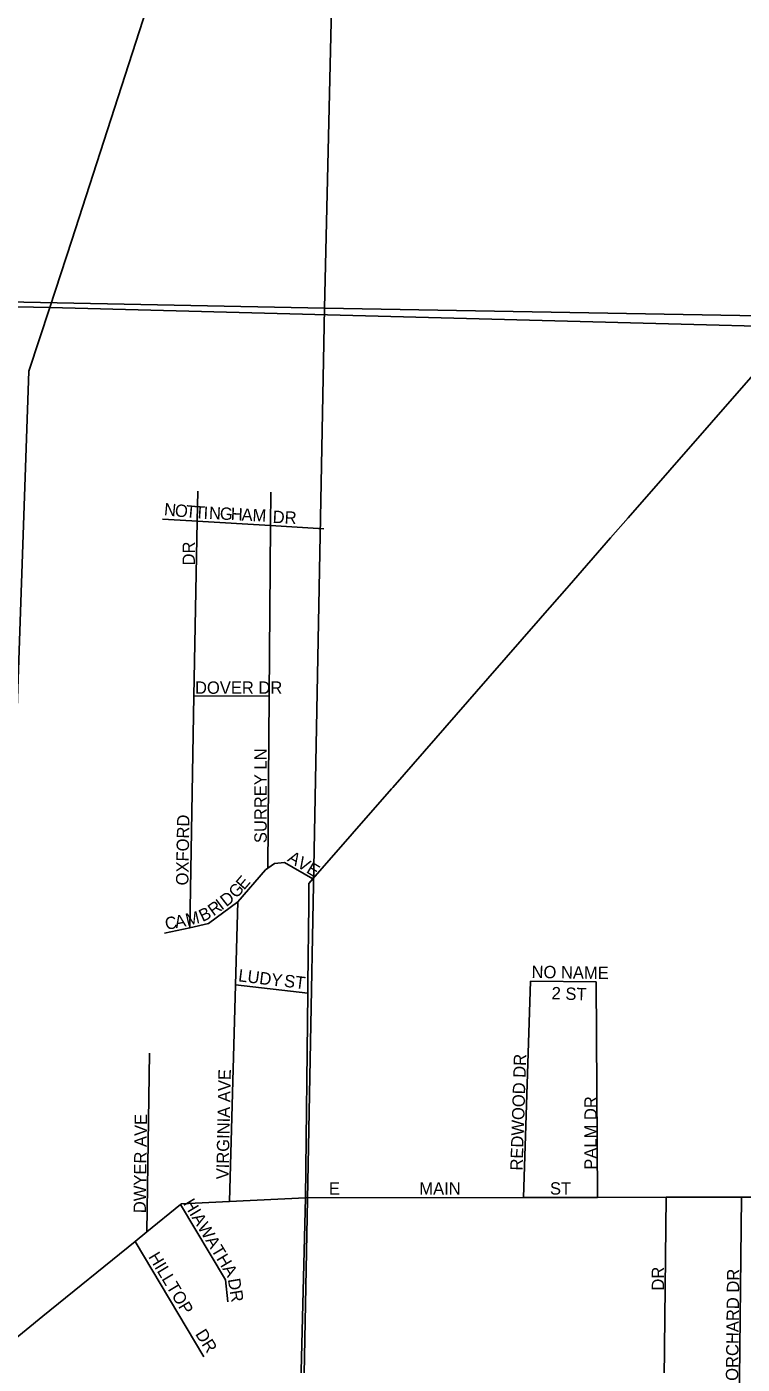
# Model space of a CAD drawing. Extents: x -784 to 1375, y -225 to 440.
# Drawn here: x 310.15 to 321.44, y 368.36 to 389.47 of the extents above; entities that cross this region are included whole.
import ezdxf

# ---------------------------------------------------------------- set-up
doc = ezdxf.new("R2010")
doc.units = 0
for name, color, linetype in [('GM_X_City_Street', 7, 'Continuous'), ('GM_X_City_Street_Text', 7, 'Continuous'), ('GM_X_Section', 7, 'Continuous'), ('GM_X_State_Route', 7, 'Continuous'), ('GM_X_Township_Road', 7, 'Continuous')]:
    doc.layers.add(name, color=color, linetype=linetype)

msp = doc.modelspace()

# ---------------------------------------------------------------- linework, layer by layer
at = {"layer": 'GM_X_City_Street'}
for points in [[(310.857, 386.101), (312.207, 390.273)], [(309.607, 368.471), (309.66, 369.552), (309.713, 371.243), (309.818, 374.657), (309.997, 378.712), (310.179, 384.035), (310.514, 385.041), (310.857, 386.101)], [(309.482, 385.059), (309.482, 385.059), (310.514, 385.041)], [(310.514, 385.041), (320.278, 384.782)], [(312.724, 375.249), (312.788, 378.906), (312.837, 381.666), (312.846, 382.141)], [(313.956, 376.19), (313.976, 378.911), (313.997, 381.597), (314.001, 382.122)], [(312.293, 381.699), (312.756, 381.671)], [(312.756, 381.671), (312.756, 381.671), (312.837, 381.666), (313.997, 381.597), (314.836, 381.547)], [(312.788, 378.906), (313.976, 378.911)], [(312.321, 375.164), (312.724, 375.249), (313.016, 375.313), (313.48, 375.655), (313.916, 376.162), (313.956, 376.19), (314.06, 376.261), (314.217, 376.28), (314.666, 376.021)], [(313.347, 370.925), (313.443, 374.347), (313.48, 375.655)], [(317.989, 370.99), (318.101, 374.403)], [(318.101, 374.403), (319.138, 374.393)], [(319.158, 370.992), (319.138, 374.393)], [(313.443, 374.347), (314.584, 374.213)], [(312.045, 370.446), (312.088, 373.266)], [(314.181, 355.025), (314.287, 359.97), (314.314, 361.184), (314.34, 362.327), (314.37, 363.611), (314.482, 368.251), (314.548, 370.985)], [(314.37, 363.611), (316.423, 363.56), (319.28, 363.488), (319.398, 363.485), (319.707, 363.569), (319.94, 363.718), (320.059, 363.98), (320.099, 364.162), (320.152, 364.4), (320.207, 367.666), (320.241, 370.994)], [(314.548, 370.985), (317.989, 370.99), (319.158, 370.992), (320.241, 370.994), (320.337, 370.994), (320.337, 370.994)], [(320.337, 370.994), (321.428, 370.996), (322.198, 370.997)], [(321.394, 367.658), (321.428, 370.996)], [(313.324, 369.344), (313.285, 369.689), (312.577, 370.877)], [(312.942, 368.475), (311.86, 370.297)]]:
    msp.add_lwpolyline(points, dxfattribs=at)
at = {"layer": 'GM_X_Section'}
msp.add_lwpolyline([(311.752, 405.896), (315.331, 405.821), (314.846, 385.028), (293.747, 385.447), (294.035, 399.712)], dxfattribs=at)
for points in [[(315.331, 405.821), (335.943, 405.436), (335.412, 384.667), (314.846, 385.028)], [(293.747, 385.447), (314.846, 385.028), (314.451, 364.338), (293.485, 364.699)], [(314.846, 385.028), (335.412, 384.667), (334.976, 363.947), (314.451, 364.338)]]:
    msp.add_lwpolyline(points, close=True, dxfattribs=at)
at = {"layer": 'GM_X_State_Route'}
for points in [[(319.641, 381.718), (322.271, 384.729), (322.411, 384.889)], [(319.364, 381.401), (319.641, 381.718)], [(318.672, 380.609), (318.709, 380.65), (319.364, 381.401)], [(318.257, 380.133), (318.291, 380.172), (318.672, 380.609)], [(317.427, 379.182), (318.257, 380.133)], [(315.904, 377.439), (315.925, 377.463), (317.427, 379.182)], [(314.599, 375.613), (314.6, 375.632), (314.603, 375.949), (314.666, 376.021), (315.904, 377.439)], [(314.585, 374.351), (314.585, 374.365), (314.599, 375.613)], [(314.548, 370.985), (314.584, 374.213), (314.585, 374.351)], [(310.402, 369.115), (311.86, 370.297), (312.045, 370.446), (312.577, 370.877), (312.59, 370.888), (313.347, 370.925), (314.548, 370.985)], [(309.286, 368.21), (309.607, 368.471), (310.402, 369.115)]]:
    msp.add_lwpolyline(points, dxfattribs=at)
at = {"layer": 'GM_X_Township_Road'}
msp.add_lwpolyline([(320.278, 384.782), (322.271, 384.729)], dxfattribs=at)

# ---------------------------------------------------------------- texts
at = {"layer": 'GM_X_City_Street_Text'}
for s, height, rotation, p in [('N', 0.195, 354.5058, (312.309, 381.76)), ('O', 0.195, 354.5129, (312.48, 381.743)), ('T', 0.195, 354.6371, (312.652, 381.727)), ('T', 0.195, 356.1561, (312.794, 381.714)), ('I', 0.195, 357.1952, (312.935, 381.704)), ('N', 0.195, 357.2653, (313.021, 381.7)), ('G', 0.195, 357.2682, (313.193, 381.692)), ('H', 0.195, 357.2682, (313.365, 381.684)), ('A', 0.195, 357.2682, (313.536, 381.675)), ('M', 0.195, 357.2685, (313.708, 381.667)), ('DR', 0.1953, 356.9889, (314.026, 381.64)), ('DR', 0.1953, 90, (312.802, 380.967)), ('DOVER DR', 0.1953, 0, (312.804, 378.941)), ('SURREY LN', 0.1953, 90, (313.936, 376.584)), ('OXFORD', 0.1953, 88.9946, (312.698, 375.915)), ('AVE', 0.1953, 329.0369, (314.249, 376.306)), ('E', 0.195, 49.4242, (313.578, 375.833)), ('G', 0.195, 47.6139, (313.457, 375.701)), ('R', 0.195, 35.9844, (313.096, 375.424)), ('I', 0.195, 36.74, (313.224, 375.517)), ('D', 0.195, 38.1624, (313.297, 375.571)), ('C', 0.195, 10.9468, (312.35, 375.211)), ('A', 0.195, 10.9486, (312.502, 375.24)), ('M', 0.195, 13.3167, (312.68, 375.275)), ('B', 0.195, 25.5355, (312.923, 375.337)), ('LUDY', 0.1953, 352.6981, (313.479, 374.404)), ('NO NAME', 0.1953, 359.1053, (318.115, 374.455)), ('ST', 0.1953, 352.8653, (314.201, 374.318)), ('2 ST', 0.1953, 357.8801, (318.43, 374.12)), ('REDWOOD DR', 0.1953, 88.1724, (317.975, 371.412)), ('VIRGINIA AVE', 0.19531, 88.794, (313.334, 371.274)), ('PALM DR', 0.1953, 90, (319.146, 371.428)), ('DWYER AVE', 0.1953, 89.3094, (312.028, 370.741)), ('E', 0.195, 0, (314.918, 371.035)), ('MAIN', 0.1953, 0, (316.345, 371.035)), ('ST', 0.1953, 0, (318.407, 371.035)), ('HIAWATHA', 0.1953, 300.964, (312.612, 370.897)), ('HILLTOP', 0.1953, 300.9647, (312.062, 370.055)), ('DR', 0.1953, 279.4643, (313.321, 369.698)), ('DR', 0.1953, 90, (320.209, 369.52)), ('ORCHARD DR', 0.1953, 89.3707, (321.378, 368.094)), ('DR', 0.1953, 302.0078, (312.801, 368.835))]:
    msp.add_text(s, height=height, rotation=rotation, dxfattribs=at).set_placement(p)

doc.saveas('drawing.dxf')
